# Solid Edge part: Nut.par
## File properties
Author: Deepak Maini
Template: normal.par
Last saved by: CADCIM
Revision: 4
Application: Solid Edge
Accuracy: 0.99
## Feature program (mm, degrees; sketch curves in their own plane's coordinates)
sketch for "unnamed Protrusion 1" plane through (0, 0, 0) normal (0, 0, 1) x-axis (1, 0, 0)
  line (-7.5, 12.9904) -> (-15, 0)
  line (-15, 0) -> (-7.5, -12.9904)
  line (-7.5, -12.9904) -> (7.5, -12.9904)
  line (7.5, -12.9904) -> (15, 0)
  line (15, 0) -> (7.5, 12.9904)
  line (7.5, 12.9904) -> (-7.5, 12.9904)
extrude "unnamed Protrusion 1" add finite 12 symmetric
sketch for "unnamed RevolvedCutout 1" plane through (0, 0, 0) normal (0, -1, 0) x-axis (1, 0, 0)
  arc centre (10, 1) radius 5 from (10, 6) to (15, 1) cw
  line (15, 6) -> (15, 1)
  line (15, 6) -> (10, 6)
revolve "unnamed RevolvedCutout 1" cut full turn 360 deg
mirror "unnamed Mirror 1" of "unnamed RevolvedCutout 1" about plane through (0, 0, 0) normal (0, 0, 1)
revolve "unnamed RevolvedCutout 2" cut full turn 360 deg
sketch for "Hole_1" plane through (0, 0, 6) normal (0, 0, 1) x-axis (0, 1, 0)
  hole centre (0, 0) bore radius 6
hole "Hole_1" diameter 12 through
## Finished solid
Body 1: solid body, 11 faces, 22 edges, 12 vertices.
  Faces by surface: plane 8, torus 2, cylinder 1
  Edges by curve: intersection 12, line 6, circle 4
Bounding box of the edges (mm; curved faces can reach further): 30.000 x 25.981 x 12.000, from (-15, -12.9904, -6) to (15, 12.9904, 6).
Cylindrical faces by radius (mm): R6 x1
Toroidal faces (ring radius, tube radius in mm): R10 r5 x2
Planar faces by outward normal: +y 1, +z 1, -y 1, -z 1, oblique 4
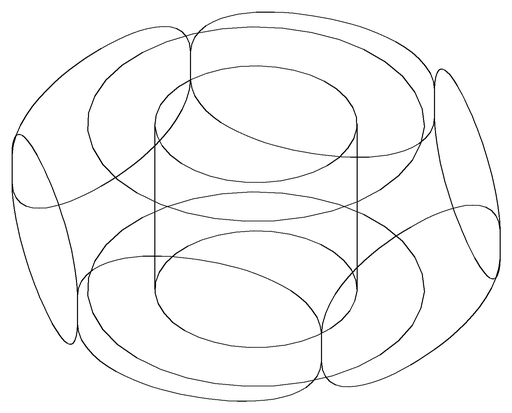
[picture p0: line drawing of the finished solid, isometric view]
